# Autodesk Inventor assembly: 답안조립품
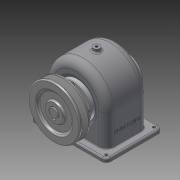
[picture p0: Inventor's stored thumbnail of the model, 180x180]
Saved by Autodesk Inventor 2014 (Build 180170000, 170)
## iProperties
Created: 2016-02
Part Number: 답안조립품
Document SubType Name: Assembly
Designer: Owner
Author: Owner
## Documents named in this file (16)
- C:\Documents and Settings\Owner\바탕 화면\460105V1002\답안조립품.iam
- C:\Documents and Settings\Owner\바탕 화면\460105V1002\본체.ipt
- C:\Documents and Settings\Owner\바탕 화면\460105V1002\오일씰 28 40 8.ipt
- C:\Documents and Settings\Owner\바탕 화면\460105V1002\뒤커버.ipt
- C:\Documents and Settings\Owner\바탕 화면\460105V1002\베어링 6203.ipt
- C:\Documents and Settings\Owner\바탕 화면\460105V1002\앞커버.ipt
- C:\Documents and Settings\Owner\바탕 화면\460105V1002\V-벨트풀리.ipt
- C:\Documents and Settings\Owner\바탕 화면\460105V1002\부시1.ipt
- C:\Documents and Settings\Owner\바탕 화면\460105V1002\부시2.ipt
- C:\Documents and Settings\Owner\바탕 화면\460105V1002\스퍼기어.ipt
- C:\Documents and Settings\Owner\바탕 화면\460105V1002\축.ipt
- C:\Documents and Settings\Owner\바탕 화면\460105V1002\키 - 6 x 6 x 22.ipt
- C:\Documents and Settings\Owner\바탕 화면\460105V1002\키 - 5 x 5 x 18.ipt
- C:\Documents and Settings\Owner\바탕 화면\460105V1002\멈춤나사 - M4x10.ipt
- C:\Documents and Settings\Owner\바탕 화면\460105V1002\볼트 M3 x 8.ipt
- C:\Documents and Settings\Owner\바탕 화면\460105V1002\볼트 M3 x 10.ipt
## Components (9 placed, 3 different names)
1. V-벨트풀리:1 — 각도:4
2. ISO 4762 M3 x 8:1
3. ISO 4762 M3 x 8:2
4. ISO 4762 M3 x 8:3
5. ISO 4762 M3 x 8:4
6. ISO 4762 M3 x 10:1
7. ISO 4762 M3 x 10:2
8. ISO 4762 M3 x 10:3
9. ISO 4762 M3 x 10:4
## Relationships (1: Angle 1)
- 각도:4 [Angle]: V-벨트풀리:1
